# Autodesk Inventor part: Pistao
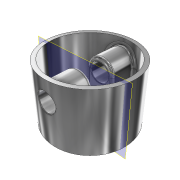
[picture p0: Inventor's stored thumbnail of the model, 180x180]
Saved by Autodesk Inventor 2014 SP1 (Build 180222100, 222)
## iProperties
Created: 2013-12
Part Number: Pistao
Material: Generic
Document SubType Name: Modeling
Designer: User
Density: 1 g/cm^3
Appearance: Chrome - Polished
Author: User
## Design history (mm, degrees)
sketch "Sketch1"
  geometry: C1 r 7 at (0, 0); 1 further point
  constraints: 1 centre point, 1 coincident
  dimensions: "d0" = 14 diameter of C1
extrude "Extrusion1" new body sketch "Sketch1" distance "d1" = 10; taper "d2" = 0 deg
sketch "Sketch2"
  geometry: C1 r 7 at (0, 0) reference; C2 r 6.35 at (0, 0)
  constraints: 1 centre point, 1 coincident
  dimensions: "d3" = 12.7 diameter of C2
extrude "Extrusion2" cut sketch "Sketch2" distance "d4" = 7.5; taper "d5" = 0 deg
workplane "Work Plane1"
sketch "Sketch3"
  geometry: L1 (-6.35, 10)-(6.35, 10) reference; L2 (-2.2, 6.8)-(-2.2, 2.5); L3 (2.2, 6.8)-(2.2, 2.5); L4 (-6.35, 2.5)-(6.35, 2.5) reference; A1 r 2.2 centre (0, 6.8) between (2.2, 6.8) and (-2.2, 6.8); 1 further point
  constraints: 4 end point, 2 point on circle, 2 point on line, 2 tangent, 1 centre point, 1 parallel, 1 perpendicular
  dimensions: "d7" = 4.4 diameter of A1; "d8" = 3.2 distance from line of L1 A1.centre
extrude "Extrusion3" join sketch "Sketch3" stored distance "d9" = 7.5; taper "d10" = 0 deg
mirror "Mirror1"
sketch "Sketch4"
  geometry: C1 r 1.5 at (0, 0); A1 r 2.2 centre (0, 0) between (2.2, 0) and (-2.2, 0) reference; 1 further point
  constraints: 1 centre point, 1 coincident
  dimensions: "d11" = 3 diameter of C1
extrude "Extrusion4" cut sketch "Sketch4" stored distance "d12" = 7.5; taper "d13" = 0 deg
fillet "Fillet1" dims "d14" = 0.5
chamfer "Chamfer1" distance "d15" = 0.1; stored, may be unused: second distance "d16" = 2, angle "d17" = 45 deg
chamfer "Chamfer2" distance "d18" = 0.5; stored, may be unused: second distance "d19" = 2, angle "d20" = 45 deg
body "Solid1"
other parameters: "d6" = -1.7
